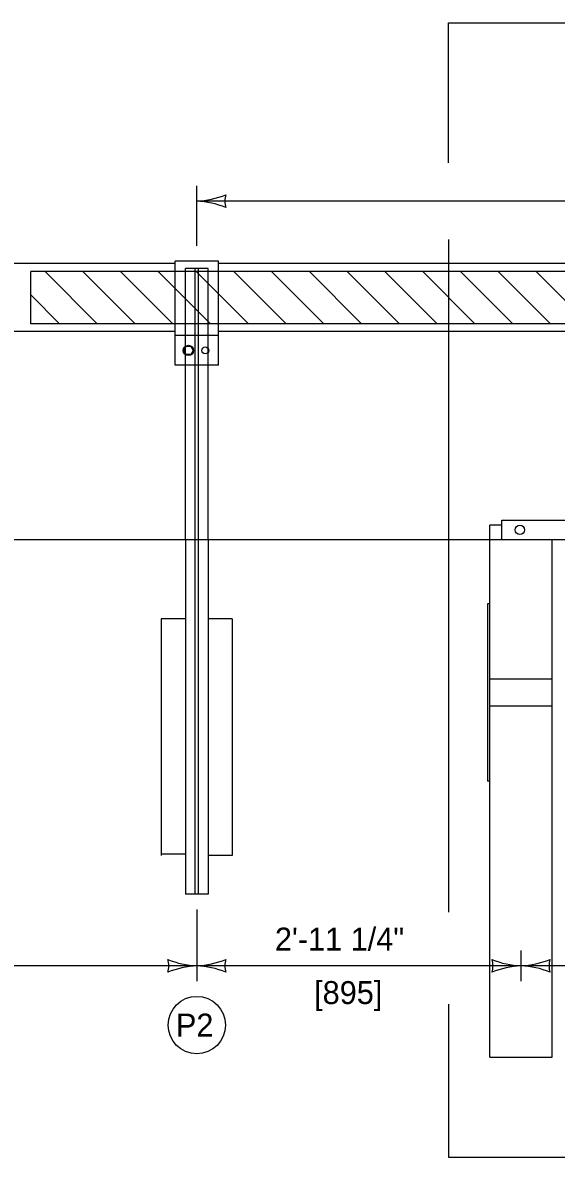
# Model space of a CAD drawing. Extents: x 49991.4 to 50021, y 49987.6 to 50011.4.
# Drawn here: x 50012.718 to 50014.114, y 49992.718 to 49995.687 of the extents above; entities that cross this region are included whole.
import ezdxf

# ---------------------------------------------------------------- set-up
doc = ezdxf.new("R2010")
doc.units = 0
for name, color, linetype in [('Level 1', 7, 'Continuous'), ('Level 2', 7, 'Continuous'), ('Level 3', 7, 'Continuous'), ('Level 4', 7, 'Continuous'), ('Level 5', 7, 'Continuous'), ('Level 6', 7, 'Continuous')]:
    doc.layers.add(name, color=color, linetype=linetype)

msp = doc.modelspace()

# ---------------------------------------------------------------- linework, layer by layer
at = {"layer": 'Level 1'}
for p, q in [((50013.1169, 49995.0567), (50011.4076, 49995.0567)), ((50013.1169, 49994.7908), (50013.1169, 49995.0629)), ((50013.2309, 49995.0629), (50013.1169, 49995.0629)), ((50013.2309, 49994.7908), (50013.2309, 49995.0629)), ((50015.4527, 49995.0567), (50013.2309, 49995.0567)), ((50013.1169, 49994.8794), (50011.4076, 49994.8794)), ((50013.2309, 49994.8683), (50013.1169, 49994.8683)), ((50015.4527, 49994.8794), (50013.2309, 49994.8794)), ((50013.2309, 49994.7908), (50013.1169, 49994.7908)), ((50013.1443, 49994.335), (50013.1443, 49994.7908)), ((50013.2034, 49994.335), (50013.2034, 49994.7908)), ((50013.972, 49994.3852), (50015.9656, 49994.3852)), ((50013.972, 49994.335), (50013.972, 49994.3852)), ((50013.972, 49994.3723), (50013.9406, 49994.3723)), ((50013.9406, 49994.335), (50013.9406, 49994.3723)), ((49999.9212, 49994.335), (50016.2933, 49994.335))]:
    msp.add_line(p, q, dxfattribs=at)
msp.add_lwpolyline([(50013.1458, 49994.8404), (50013.1581, 49994.8402), (50013.1641, 49994.8294), (50013.1579, 49994.8188), (50013.1456, 49994.8191), (50013.1395, 49994.8297)], close=True, dxfattribs=at)
for centre, radius in [((50013.1518, 49994.8296), 0.0135), ((50013.1959, 49994.8296), 0.00904), ((50014.0191, 49994.3601), 0.0123)]:
    msp.add_circle(centre, radius, dxfattribs=at)
at = {"layer": 'Level 2'}
msp.add_circle((50013.1738, 49993.0644), 0.075, dxfattribs=at)
at = {"layer": 'Level 3'}
for p, q in [((50013.1739, 49995.1029), (50013.1739, 49995.2602)), ((50015.6047, 49995.2202), (50013.1739, 49995.2202)), ((50013.1738, 49993.3671), (50013.1738, 49993.1794)), ((50014.0221, 49993.1794), (50014.0221, 49993.2594)), ((50013.1738, 49993.2194), (50011.3508, 49993.2194)), ((50014.0221, 49993.2194), (50013.1738, 49993.2194)), ((50015.9211, 49993.2194), (50014.0221, 49993.2194))]:
    msp.add_line(p, q, dxfattribs=at)
for centre, radius, start, end in [((50013.1624, 49995.4529), 0.233, 272.8273, 292.0772), ((50013.1647, 49994.9981), 0.2223, 67.456, 87.6395), ((50013.3021, 49995.2202), 0.0548, 162.1388, 197.8612), ((50013.183, 49993.4415), 0.2223, 247.456, 267.6395), ((50013.0456, 49993.2194), 0.0548, 342.1388, 17.8612), ((50013.1623, 49993.4521), 0.233, 272.8273, 292.0772), ((50013.302, 49993.2194), 0.0548, 162.1388, 197.8612), ((50014.0313, 49993.4415), 0.2223, 247.456, 267.6395), ((50013.8939, 49993.2194), 0.0548, 342.1388, 17.8612), ((50014.0106, 49993.4521), 0.233, 272.8273, 292.0772), ((50014.1503, 49993.2194), 0.0548, 162.1388, 197.8612), ((50013.1853, 49992.9867), 0.233, 92.8273, 112.0772), ((50013.1646, 49992.9973), 0.2223, 67.456, 87.6395), ((50014.0336, 49992.9867), 0.233, 92.8273, 112.0772), ((50014.0129, 49992.9973), 0.2223, 67.456, 87.6395)]:
    msp.add_arc(centre, radius, start, end, dxfattribs=at)
at = {"layer": 'Level 4'}
for p, q in [((50013.2034, 49995.0439), (50013.1443, 49995.0439)), ((50013.1443, 49994.7908), (50013.1443, 49995.0439)), ((50013.1693, 49993.4071), (50013.1693, 49995.0439)), ((50013.1784, 49993.4071), (50013.1784, 49995.0439)), ((50013.2034, 49994.7908), (50013.2034, 49995.0439)), ((50012.7392, 49994.8996), (50012.7392, 49995.0363)), ((50014.5412, 49995.0363), (50012.7392, 49995.0363)), ((50014.5412, 49994.8996), (50012.7392, 49994.8996)), ((50013.1443, 49994.335), (50013.1443, 49993.4071)), ((50013.2034, 49994.335), (50013.2034, 49993.4071)), ((50013.9406, 49992.9805), (50013.9406, 49994.335)), ((50014.1036, 49992.9805), (50014.1036, 49994.335)), ((50013.9406, 49994.1662), (50013.9342, 49994.1662)), ((50013.9342, 49994.1662), (50013.9342, 49993.7023)), ((50013.1443, 49994.127), (50013.0809, 49994.127)), ((50013.0809, 49994.127), (50013.0809, 49993.5085)), ((50013.2666, 49994.127), (50013.2034, 49994.127)), ((50013.2666, 49994.127), (50013.2666, 49993.5085)), ((50014.1036, 49993.9696), (50013.9406, 49993.9696)), ((50014.1036, 49993.8987), (50013.9406, 49993.8987)), ((50013.9406, 49993.7023), (50013.9342, 49993.7023)), ((50013.1443, 49993.5119), (50013.0809, 49993.5119)), ((50013.2666, 49993.5085), (50013.2034, 49993.5085)), ((50013.2034, 49993.4071), (50013.1443, 49993.4071)), ((50013.9406, 49992.9805), (50014.1036, 49992.9805))]:
    msp.add_line(p, q, dxfattribs=at)
at = {"layer": 'Level 5'}
for p, q in [((50012.9133, 49994.8996), (50012.7767, 49995.0363)), ((50013.0122, 49994.8996), (50012.8755, 49995.0363)), ((50013.1109, 49994.8996), (50012.9743, 49995.0363)), ((50013.2099, 49994.8996), (50013.0731, 49995.0363)), ((50013.3087, 49994.8996), (50013.1719, 49995.0363)), ((50013.4075, 49994.8996), (50013.2707, 49995.0363)), ((50013.5063, 49994.8996), (50013.3696, 49995.0363)), ((50013.6051, 49994.8996), (50013.4684, 49995.0363)), ((50013.704, 49994.8996), (50013.5673, 49995.0363)), ((50013.8027, 49994.8996), (50013.6662, 49995.0363)), ((50013.9017, 49994.8996), (50013.7649, 49995.0363)), ((50014.0004, 49994.8996), (50013.8637, 49995.0363)), ((50014.0992, 49994.8996), (50013.9627, 49995.0363)), ((50014.1982, 49994.8996), (50014.0615, 49995.0363)), ((50012.8145, 49994.8996), (50012.7392, 49994.975))]:
    msp.add_line(p, q, dxfattribs=at)
at = {"layer": 'Level 6'}
for points in [[(50013.832, 49995.3202), (50013.832, 49995.6872), (50016.4251, 49995.6872)], [(50013.832, 49995.1202), (50013.832, 49993.3594)], [(50013.832, 49993.1194), (50013.832, 49992.7184), (50016.4251, 49992.7184)]]:
    msp.add_lwpolyline(points, dxfattribs=at)

# ---------------------------------------------------------------- texts
at = {"layer": 'Level 2'}
for s, p in [('2\'-11 1/4"', (50013.3782, 49993.2594)), ('[895]', (50013.4808, 49993.1194)), ('P2', (50013.1192, 49993.0344))]:
    msp.add_text(s, height=0.06, dxfattribs=at).set_placement(p)

doc.saveas('drawing.dxf')
